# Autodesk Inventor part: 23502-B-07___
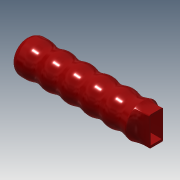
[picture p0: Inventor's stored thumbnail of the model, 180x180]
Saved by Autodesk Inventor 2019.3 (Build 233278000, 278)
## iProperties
Created: 2010-06
Part Number: 23502-B-07___
Material: Ogólny
Document SubType Name: Modeling
Designer: CADENGINEERING4
Density: 1 g/cm^3
Appearance: Czerwona
Author: CADENGINEERING4
Revision Number: ANY
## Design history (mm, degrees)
feature "NONE"
node "Bryła1"
